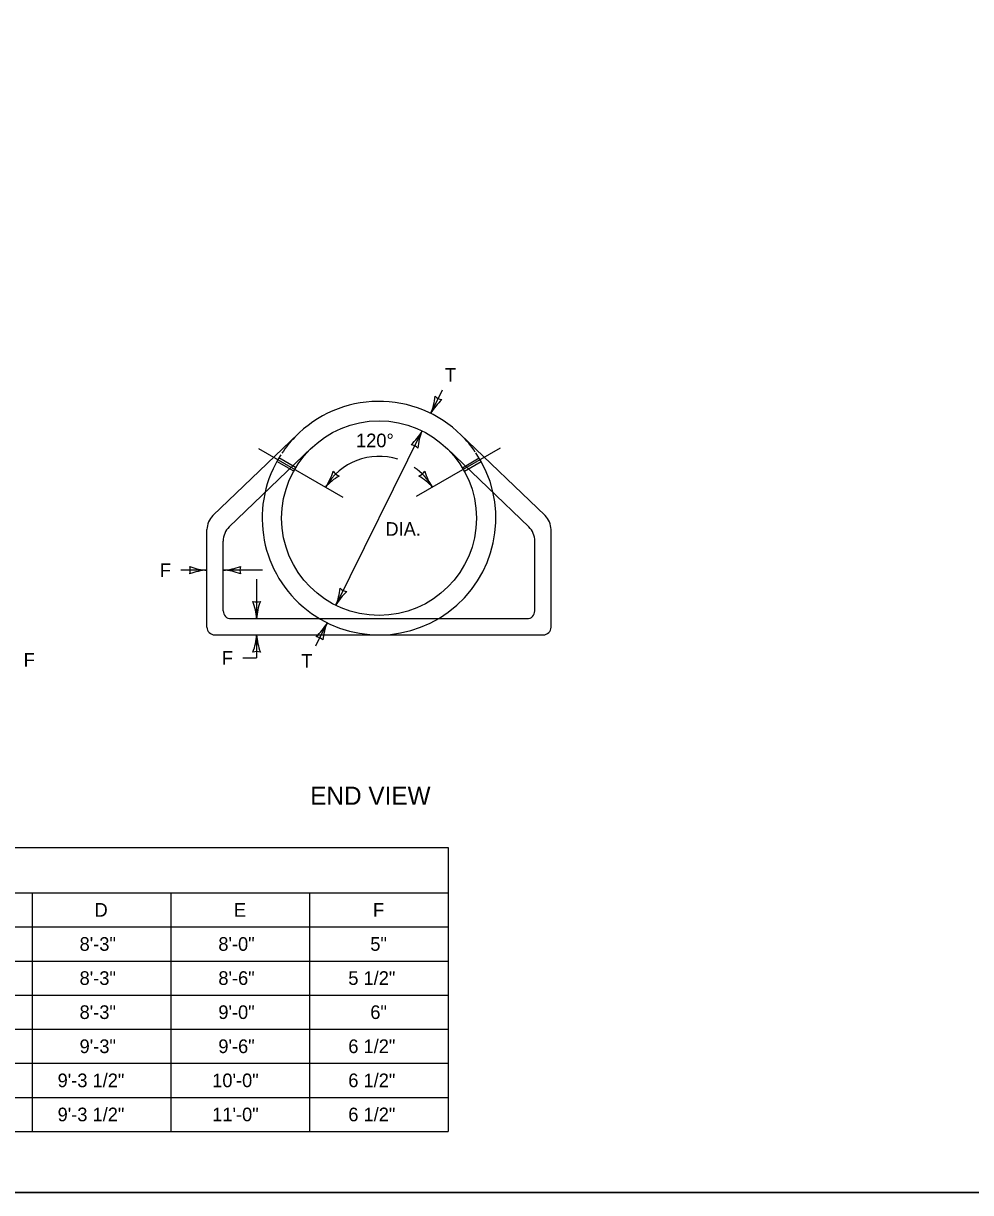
# Model space of a CAD drawing. Extents: x 49991.4 to 50021, y 49987.6 to 50011.4.
# Drawn here: x 50004.5 to 50008.67, y 49987.8 to 49992.94 of the extents above; entities that cross this region are included whole.
import ezdxf

# ---------------------------------------------------------------- set-up
doc = ezdxf.new("R2010")
doc.units = 0
for name, color, linetype in [('Level 1', 7, 'Continuous'), ('Level 2', 7, 'Continuous'), ('Level 3', 7, 'Continuous'), ('Level 4', 7, 'Continuous'), ('Level 5', 7, 'Continuous')]:
    doc.layers.add(name, color=color, linetype=linetype)

msp = doc.modelspace()

# ---------------------------------------------------------------- linework, layer by layer
at = {"layer": 'Level 1'}
for p, q in [((50005.7097, 49991.1365), (50005.3354, 49990.7771)), ((50006.4229, 49991.1349), (50006.7955, 49990.7771)), ((50005.769, 49991.0748), (50005.4069, 49990.727)), ((50006.3637, 49991.0731), (50006.724, 49990.727)), ((50005.3091, 49990.2865), (50005.3091, 49990.7154)), ((50006.8218, 49990.2865), (50006.8218, 49990.7154)), ((50005.3805, 49990.3579), (50005.3805, 49990.6653)), ((50006.7504, 49990.3579), (50006.7504, 49990.6653)), ((50005.4148, 49990.3237), (50006.7161, 49990.3237)), ((50005.3434, 49990.2523), (50006.7875, 49990.2523))]:
    msp.add_line(p, q, dxfattribs=at)
msp.add_lwpolyline([(49999.3835, 49998.9992), (50016.7501, 49998.9992), (50016.7501, 49987.7988), (49999.3835, 49987.7988)], close=True, dxfattribs=at)
msp.add_circle((50006.0655, 49990.766), 0.4281, dxfattribs=at)
for centre, radius, start, end in [((50006.0655, 49990.766), 0.5137, 45.3824, 135.9308), ((50005.3947, 49990.7154), 0.0856, 133.8358, 180), ((50006.7362, 49990.7154), 0.0856, 0, 46.1636), ((50005.4661, 49990.6653), 0.0856, 133.8272, 180), ((50006.6648, 49990.6653), 0.0856, 0, 46.1643), ((50005.4148, 49990.3579), 0.0342, 180, 270), ((50006.7161, 49990.3579), 0.0342, 270, 0), ((50005.3434, 49990.2865), 0.0342, 180, 270), ((50006.7875, 49990.2865), 0.0342, 270, 0)]:
    msp.add_arc(centre, radius, start, end, dxfattribs=at)
at = {"layer": 'Level 2'}
for p, q in [((50000.8802, 49989.3176), (50006.3702, 49989.3176)), ((50006.3702, 49989.3176), (50006.3702, 49988.0676)), ((50000.8802, 49989.1176), (50006.3702, 49989.1176)), ((50004.5402, 49989.1176), (50004.5402, 49988.0676)), ((50005.1502, 49989.1176), (50005.1502, 49988.0676)), ((50005.7602, 49989.1176), (50005.7602, 49988.0676)), ((50000.8802, 49988.9676), (50006.3702, 49988.9676)), ((50000.8802, 49988.8176), (50006.3702, 49988.8176)), ((50000.8802, 49988.6676), (50006.3702, 49988.6676)), ((50000.8802, 49988.5176), (50006.3702, 49988.5176)), ((50000.8802, 49988.3676), (50006.3702, 49988.3676)), ((50000.8802, 49988.2176), (50006.3702, 49988.2176)), ((50000.8802, 49988.0676), (50006.3702, 49988.0676)), ((49999.3835, 49987.7988), (50016.7501, 49987.7988))]:
    msp.add_line(p, q, dxfattribs=at)
at = {"layer": 'Level 3'}
for p, q in [((50006.2932, 49991.2264), (50006.3444, 49991.33)), ((50005.8756, 49990.3823), (50006.2552, 49991.1497)), ((50005.3091, 49990.5371), (50005.1948, 49990.5371)), ((50005.5539, 49990.5371), (50005.3805, 49990.5371)), ((50005.5275, 49990.4971), (50005.5275, 49990.3237)), ((50005.7874, 49990.2039), (50005.8377, 49990.3055)), ((50005.5275, 49990.2523), (50005.5275, 49990.1509)), ((50005.4668, 49990.1509), (50005.5275, 49990.1509))]:
    msp.add_line(p, q, dxfattribs=at)
for centre, radius, start, end in [((50006.0795, 49991.3192), 0.233, 336.5283, 355.7782), ((50006.4883, 49991.1198), 0.2223, 131.157, 151.3405), ((50006.35, 49991.3414), 0.0548, 225.8398, 261.5622), ((50006.0602, 49991.2564), 0.2223, 311.1364, 331.3199), ((50006.4689, 49991.0568), 0.233, 156.5077, 175.7575), ((50006.1984, 49991.0348), 0.0548, 45.8192, 81.5415), ((50006.0655, 49990.766), 0.2718, 72.1571, 150.0044), ((50005.6399, 49991.0365), 0.233, 324.6826, 343.9325), ((50005.9093, 49991.0027), 0.0548, 213.9941, 249.7165), ((50006.0655, 49990.766), 0.2718, 30.0137, 55.2312), ((50006.2214, 49991.0026), 0.0548, 290.4277, 326.1501), ((50006.4808, 49991.0324), 0.2223, 195.7449, 215.9284), ((50005.9991, 49990.7574), 0.2223, 119.3113, 139.4948), ((50006.1253, 49990.7487), 0.233, 41.1162, 60.3661), ((50005.3183, 49990.7592), 0.2223, 247.456, 267.6395), ((50005.1809, 49990.5371), 0.0548, 342.1388, 17.8612), ((50005.369, 49990.7698), 0.233, 272.8273, 292.0772), ((50005.5087, 49990.5371), 0.0548, 162.1388, 197.8612), ((50005.3206, 49990.3044), 0.233, 92.8273, 112.0772), ((50005.3713, 49990.3149), 0.2223, 67.456, 87.6395), ((50005.6619, 49990.4752), 0.233, 336.5077, 355.7575), ((50006.0706, 49990.2756), 0.2223, 131.1364, 151.3199), ((50005.9324, 49990.4972), 0.0548, 225.8192, 261.5415), ((50005.5275, 49990.4519), 0.0548, 252.1388, 287.8612), ((50005.2948, 49990.3122), 0.233, 2.8273, 22.0772), ((50005.7496, 49990.3145), 0.2223, 157.456, 177.6395), ((50005.6427, 49990.4123), 0.2223, 311.117, 331.3005), ((50006.0514, 49990.2126), 0.233, 156.4883, 175.7381), ((50005.3054, 49990.2615), 0.2223, 337.456, 357.6395), ((50005.7602, 49990.2638), 0.233, 182.8273, 202.0772), ((50005.7808, 49990.1906), 0.0548, 45.7998, 81.5221), ((50005.5275, 49990.1241), 0.0548, 72.1388, 107.8612)]:
    msp.add_arc(centre, radius, start, end, dxfattribs=at)
at = {"layer": 'Level 4'}
for p, q in [((50005.6907, 49990.9721), (50005.6161, 49991.015)), ((50005.6987, 49990.988), (50005.6251, 49991.0305)), ((50006.432, 49990.9879), (50006.5061, 49991.0307)), ((50006.4408, 49990.9724), (50006.5148, 49991.0151))]:
    msp.add_line(p, q, dxfattribs=at)
for start, end in [(136.134, 146.1916), (34.4729, 45.2134), (147.1466, 33.9701)]:
    msp.add_arc((50006.0655, 49990.766), 0.5137, start, end, dxfattribs=at)
at = {"layer": 'Level 5'}
for p, q in [((50005.5362, 49991.0717), (50005.9061, 49990.8579)), ((50006.5988, 49991.074), (50006.2289, 49990.8604))]:
    msp.add_line(p, q, dxfattribs=at)

# ---------------------------------------------------------------- texts
at = {"layer": 'Level 2'}
for s, height, p in [('T', 0.06, (50006.3557, 49991.3659)), ('120°', 0.06, (50005.9645, 49991.0777)), ('DIA.', 0.06, (50006.0936, 49990.6883)), ('F', 0.06, (50005.1024, 49990.5071)), ('F', 0.06, (50005.3744, 49990.1209)), ('F', 0.06, (50004.5032, 49990.1127)), ('T', 0.06, (50005.724, 49990.1081)), ('END VIEW', 0.08, (50005.7631, 49989.505)), ('D', 0.06, (50004.8149, 49989.0126)), ('E', 0.06, (50005.4272, 49989.0126)), ('F', 0.06, (50006.0391, 49989.0126)), ('8\'-3"', 0.06, (50004.7491, 49988.8626)), ('8\'-0"', 0.06, (50005.3591, 49988.8626)), ('5"', 0.06, (50006.0272, 49988.8626)), ('8\'-3"', 0.06, (50004.7491, 49988.7126)), ('8\'-6"', 0.06, (50005.3591, 49988.7126)), ('5 1/2"', 0.06, (50005.9305, 49988.7126)), ('8\'-3"', 0.06, (50004.7491, 49988.5626)), ('9\'-0"', 0.06, (50005.3591, 49988.5626)), ('6"', 0.06, (50006.0272, 49988.5626)), ('9\'-3"', 0.06, (50004.7491, 49988.4126)), ('9\'-6"', 0.06, (50005.3591, 49988.4126)), ('6 1/2"', 0.06, (50005.9305, 49988.4126)), ('9\'-3 1/2"', 0.06, (50004.6524, 49988.2626)), ('10\'-0"', 0.06, (50005.3322, 49988.2626)), ('6 1/2"', 0.06, (50005.9305, 49988.2626)), ('9\'-3 1/2"', 0.06, (50004.6524, 49988.1126)), ('6 1/2"', 0.06, (50005.9305, 49988.1126)), ('11\'-0"', 0.06, (50005.3322, 49988.1126))]:
    msp.add_text(s, height=height, dxfattribs=at).set_placement(p)

doc.saveas('drawing.dxf')
